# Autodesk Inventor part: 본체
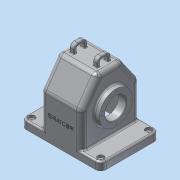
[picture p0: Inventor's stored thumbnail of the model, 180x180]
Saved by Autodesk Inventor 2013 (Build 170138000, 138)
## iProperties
Created: 2016-12
Part Number: 본체
Material: 알루미늄 6061
Document SubType Name: Modeling
Designer: dgall
Density: 2.71 g/cm^3
Mass: 1057.23 g
Surface Area: 1134.4 cm^2
Volume: 390.12 cm^3
Author: dgall
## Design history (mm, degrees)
sketch "스케치1"
  geometry: L1 (0, 0)-(150, 0); L2 (150, 0)-(150, 110); L3 (150, 110)-(0, 110); L4 (0, 110)-(0, 0)
  constraints: 8 end point, 2 parallel, 1 horizontal, 1 perpendicular
  dimensions: "d0" = 150 distance of L2.end L3.end; "d2" = 110 distance of L1.end L2.end
extrude "돌출1" new body sketch "스케치1" distance "d3" = 15; taper "d4" = 0 deg
node "작업 평면1"
sketch "스케치2"
  geometry: L1 (0, 15)-(-110, 15) reference; L2 (0, 0)-(-110, 0) reference; L3 (-110, 15)-(-110, 80); L4 (-110, 80)-(-78.491, 125); L5 (-78.491, 125)-(-31.509, 125); L6 (-31.509, 125)-(0, 80); L7 (0, 80)-(0, 15)
  constraints: 10 end point, 2 vertical, 1 equal length, 1 perpendicular
  dimensions: "d6" = 35 deg angle of L3 L4; "d7" = 35 deg angle of L7 L6; "d8" = 125 distance between parallel lines of L2 L5; "d9" = 80 distance from line of L2 L6.end
extrude "돌출2" join sketch "스케치2" stored distance "d10" = 77; taper "d11" = 0 deg
sketch "스케치3"
  geometry: L1 (125, 31.509)-(125, 78.491) reference; L2 (0, 110)-(0, 0) reference; C1 r 37.5 at (65, 55); 1 further point
  constraints: 1 centre point, 1 horizontal alignment, 1 midpoint
  dimensions: "d12" = 65 distance from line of L2 C1.centre; "d13" = 75 diameter of C1
extrude "돌출3" join sketch "스케치3" distance "d14" = 5; taper "d15" = 0 deg
sketch "스케치4"
  geometry: L1 (-125, 78.491)-(-125, 31.509) reference; L2 (0, 0)-(0, 110) reference; C1 r 31 at (-65, 55); 2 further points
  constraints: 2 midpoint, 1 centre point, 1 horizontal alignment
  dimensions: "d16" = 62 diameter of C1; "d18" = 65 distance from line of L2 C1.centre
extrude "돌출4" join sketch "스케치4" distance "d19" = 10; taper "d20" = 0 deg
fillet "모깎기1" dims "d21" = 8
fillet "모깎기2" dims "d22" = 10
hole "구멍1" diameter "d31" = 5; stored, may be unused: countersink angle "d35" = 90 deg, drill point angle "d37" = 118 deg; dims "d29" = 10, "d30" = 10, "d32" = 6, "d33" = 12, "d34" = 5, "d36" = 8
hole "구멍2" diameter "d40" = 5; stored, may be unused: countersink angle "d44" = 90 deg, drill point angle "d46" = 118 deg; dims "d38" = 10, "d39" = 10, "d41" = 6, "d42" = 12, "d43" = 5, "d45" = 8
fillet "모깎기3" dims "d47" = 3
fillet "모깎기4" dims "d48" = 3
fillet "모깎기5" dims "d49" = 10
node "작업 평면3"
node "작업 평면4"
sketch "스케치8"
  geometry: L1 (-82.583, 1.808)-(-117, 25.908) reference; L2 (-125, 31.509)-(-125, 78.491) reference; L3 (-117, 25.908)-(-125, 31.509) reference; L4 (-125, 78.491)-(-117, 84.092) reference; L5 (-117, 84.092)-(-82.583, 108.192) reference; L6 (-78.424, 105)-(-114.132, 79.997); L7 (-114.132, 79.997)-(-120, 75.888); L8 (-120, 75.888)-(-120, 34.112); L9 (-120, 34.112)-(-114.132, 30.003); L10 (-114.132, 30.003)-(-78.424, 5); L11 (-78.424, 5)-(0, 5); L12 (-78.424, 105)-(0, 105); L13 (0, 105)-(0, 5); L14 (0, 10)-(0, 0) reference; L15 (-12, 0)-(-76.847, 0) reference; L16 (-76.847, 110)-(-12, 110) reference; 2 further points
  constraints: 16 end point, 2 perpendicular, 1 equal length, 1 midpoint, 1 parallel, 4 other
  dimensions: "d51" = 5 distance between parallel lines of L8 L2; "d53" = 5 distance between parallel lines of L15 L11; "d54" = 5 distance between parallel lines of L12 L16; "d55" = 4.10874 vertical distance of L6.end L7.end
extrude "돌출5" cut sketch "스케치8" stored distance "d56" = 67; taper "d57" = 0 deg
node "작업 평면5"
sketch "스케치9"
  geometry: L1 (21.5, 102.5)-(21.5, 27.5) reference; L2 (113.5, 34)-(113.5, 96) reference; L3 (21.5, 65)-(113.5, 65); L4 (98.5, 0)-(31.5, 0) reference; L5 (45.5, 65)-(45.5, 92); L6 (45.5, 92)-(31.5, 106); L7 (31.5, 106)-(31.5, 65); L8 (31.5, 120)-(31.5, 78.424) reference; 1 further point
  constraints: 8 end point, 3 perpendicular, 3 point on line, 2 midpoint
  dimensions: "d58" = 65 distance between parallel lines of L4 L3; "d59" = 45 deg angle of L5 L6; "d60" = 54 diameter of L5.end L3; "d61" = 24 distance between parallel lines of L1 L5
revolve "회전1" sketch "스케치9" stored, may be unused: angle "d63" = 90 deg
hole "구멍3" diameter "d66" = 40; stored, may be unused: countersink angle "d70" = 90 deg, drill point angle "d72" = 118 deg; dims "d64" = 10, "d65" = 10, "d67" = 6, "d68" = 12, "d69" = 5, "d71" = 8
chamfer "모따기1" distance "d75" = 1; stored, may be unused: second distance "d76" = 2, angle "d77" = 45 deg
fillet "모깎기8" dims "d78" = 3
fillet "모깎기9" dims "d79" = 3
node "작업 평면6"
sketch "스케치12"
  geometry: L1 (-78.491, 125)-(-31.509, 125) reference; L2 (-62.5, 125)-(-62.5, 135); L3 (-62.5, 135)-(-47.5, 135); L4 (-47.5, 135)-(-47.5, 125); L5 (-42.5, 125)-(-42.5, 140); L6 (-42.5, 140)-(-67.5, 140); L7 (-67.5, 140)-(-67.5, 125); L8 (-8, 0)-(-102, 0) reference; 4 further points
  constraints: 12 end point, 5 perpendicular, 4 point on line, 3 midpoint, 2 vertical alignment, 1 parallel
  dimensions: "d81" = 15 distance of L2.end L3.end; "d85" = 140 distance between parallel lines of L8 L6; "d86" = 25 distance of L5.end L6.end; "d87" = 5 distance between parallel lines of L3 L6
extrude "돌출6" join sketch "스케치12" distance "d88" = 8; taper "d89" = 0 deg
sketch "스케치13"
  geometry: C1 r 37.5 at (0, 0) reference; 2 further points
  constraints: 1 horizontal alignment
  dimensions: "d97" = 29 distance of C1.centre point (29, 0)
hole "구멍4" sketch "스케치13" at (29, 0) diameter "d98" = 2.459; stored, may be unused: countersink angle "d102" = 90 deg, drill point angle "d104" = 118 deg; dims "d99" = 6, "d100" = 12, "d101" = 5, "d103" = 8
sketch "스케치14"
  geometry: C1 r 31 at (0, 0) reference; 2 further points
  constraints: 1 horizontal alignment
  dimensions: "d108" = 26 distance of point (-26, 0) C1.centre
hole "구멍5" sketch "스케치14" at (-26, 0) diameter "d109" = 2.459; stored, may be unused: countersink angle "d113" = 90 deg, drill point angle "d115" = 118 deg; dims "d110" = 6, "d111" = 12, "d112" = 5, "d114" = 8
sketch "스케치15"
  geometry: L1 (0, 0)-(130, 0) reference; 3 further points
  constraints: 1 midpoint, 1 vertical alignment, 1 other
  dimensions: "d120" = 45 distance from line of L1 point (65, 45)
feature "엠보싱1" sketch "스케치15" dims "d121" = 0.5, "d122" = 0
fillet "모깎기18" dims "d123" = 10
fillet "모깎기19" dims "d124" = 10
fillet "모깎기20" dims "d125" = 3
fillet "모깎기21" dims "d126" = 8
fillet "모깎기22" dims "d127" = 3
fillet "모깎기23" dims "d128" = 1
fillet "모깎기24" dims "d129" = 1
fillet "모깎기25" dims "d130" = 1
node "솔리드1"
mirror "대칭1"
mirror "대칭2"
pattern_circular "원형 패턴1" dims angle "d106" = 360 deg
pattern_circular "원형 패턴2" dims angle "d117" = 360 deg
other parameters: "d80" = -18
